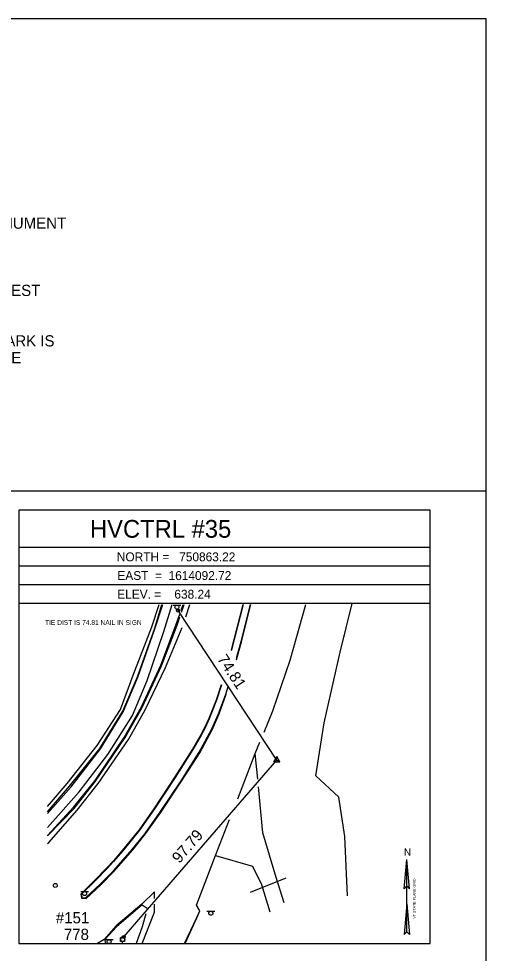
# Model space of a CAD drawing. Extents: x 1612431 to 1613071, y 750572 to 750992.
# Drawn here: x 1612946.1 to 1613071.1, y 750742 to 750992.1 of the extents above; entities that cross this region are included whole.
import ezdxf

# ---------------------------------------------------------------- set-up
doc = ezdxf.new("R2010")
doc.units = 0
for name, color, linetype in [('C_C', 7, 'Continuous'), ('CBP', 7, 'Continuous'), ('CPSM', 7, 'Continuous'), ('DCP', 7, 'Continuous'), ('DD', 7, 'Continuous'), ('Default', 7, 'Continuous'), ('LAWA', 7, 'Continuous'), ('Level 2', 7, 'Continuous'), ('LW', 7, 'Continuous'), ('NBL2', 7, 'Continuous'), ('NNA_P', 7, 'Continuous'), ('PET', 7, 'Continuous'), ('RC', 7, 'Continuous'), ('RDP', 7, 'Continuous'), ('RSW', 7, 'Continuous'), ('SSGN', 7, 'Continuous'), ('U_C', 7, 'Continuous'), ('UP', 7, 'Continuous'), ('USMH', 7, 'Continuous')]:
    doc.layers.add(name, color=color, linetype=linetype)

msp = doc.modelspace()

# ---------------------------------------------------------------- linework, layer by layer
at = {"layer": 'CBP'}
for centre, radius in [((1612988.74, 750833.73), 0.4), ((1612988.74, 750833.73), 0.0533), ((1612974.18, 750746.41), 0.4), ((1612974.18, 750746.41), 0.0533)]:
    msp.add_circle(centre, radius, dxfattribs=at)
at = {"layer": 'CPSM'}
for p, q in [((1613014.31, 750793.31), (1613015.11, 750794.69)), ((1613014.31, 750793.31), (1613015.11, 750793.77)), ((1613014.31, 750793.31), (1613015.91, 750793.31)), ((1613015.91, 750793.31), (1613015.11, 750794.69)), ((1613015.11, 750793.77), (1613015.11, 750794.69)), ((1613015.11, 750793.77), (1613015.11, 750793.77)), ((1613015.11, 750793.77), (1613015.91, 750793.31))]:
    msp.add_line(p, q, dxfattribs=at)
at = {"layer": 'DCP'}
msp.add_lwpolyline([(1613008.11, 750758.43), (1613017.6, 750762.21)], dxfattribs=at)
at = {"layer": 'DD'}
for points in [[(1612989.67, 750833.35), (1612990.37, 750835.4)], [(1612953.85, 750773.49), (1612960.93, 750780.8), (1612966.67, 750788.14), (1612974.54, 750799.79), (1612979.15, 750807.79), (1612984.29, 750818.97), (1612988.48, 750829.89), (1612989.22, 750832.06)]]:
    msp.add_lwpolyline(points, dxfattribs=at)
at = {"layer": 'Default'}
for p, q in [((1613015.11, 750793.77), (1612988.74, 750833.73)), ((1612974.18, 750746.41), (1613015.11, 750793.77))]:
    msp.add_line(p, q, dxfattribs=at)
at = {"layer": 'LAWA'}
for points in [[(1612953.85, 750781.33), (1612959.07, 750787.51), (1612967.13, 750797.64), (1612973.32, 750807.25), (1612976.7, 750816.48), (1612981.68, 750829.38), (1612983.7, 750835.4)], [(1613034.04, 750757.4), (1613033.31, 750773.27), (1613031.74, 750783.85), (1613025.53, 750789.54), (1613027.79, 750803.73), (1613032.1, 750822.61), (1613035.24, 750835.63)]]:
    msp.add_lwpolyline(points, dxfattribs=at)
at = {"layer": 'LW'}
for points in [[(1612953.85, 750779.93), (1612959.69, 750786.76), (1612967.79, 750796.88), (1612973.92, 750806.8), (1612977.86, 750816.05), (1612982.51, 750829.07), (1612984.4, 750835.4)], [(1612989.52, 750833.83), (1612990.08, 750835.4)], [(1612953.85, 750773.61), (1612960.86, 750781.22), (1612966.54, 750788.27), (1612974.34, 750799.76), (1612978.98, 750808), (1612984.15, 750819.13), (1612988.12, 750829.89), (1612989.15, 750832.77)]]:
    msp.add_lwpolyline(points, dxfattribs=at)
at = {"layer": 'NBL2'}
for p, q in [((1612431.13, 750865.8), (1613071.13, 750865.8)), ((1613056.13, 750850.63), (1612946.13, 750850.63)), ((1613056.13, 750845.63), (1612946.13, 750845.63)), ((1613056.13, 750840.63), (1612946.13, 750840.63)), ((1613056.13, 750835.63), (1612946.13, 750835.63))]:
    msp.add_line(p, q, dxfattribs=at)
for points in [[(1612431.13, 750572.13), (1613071.13, 750572.13), (1613071.13, 750992.13), (1612431.13, 750992.13)], [(1612946.13, 750744.63), (1613056.13, 750744.63), (1613056.13, 750860.63), (1612946.13, 750860.63)]]:
    msp.add_lwpolyline(points, close=True, dxfattribs=at)
at = {"layer": 'NNA_P'}
for p, q in [((1613049.19, 750759.34), (1613049.88, 750767.13)), ((1613049.89, 750747.75), (1613049.88, 750767.13)), ((1613050.58, 750759.34), (1613049.88, 750767.13)), ((1613049.19, 750759.34), (1613049.88, 750760.1)), ((1613050.58, 750759.34), (1613049.88, 750760.1)), ((1613049.89, 750755.28), (1613049.17, 750747.12)), ((1613049.88, 750755.28), (1613050.61, 750747.12)), ((1613049.89, 750747.75), (1613049.17, 750747.12)), ((1613049.89, 750747.75), (1613050.61, 750747.12))]:
    msp.add_line(p, q, dxfattribs=at)
at = {"layer": 'PET'}
for points in [[(1612990.77, 750832.08), (1612991.87, 750835.4)], [(1613006.02, 750835.4), (1613002.89, 750823.27), (1613002.89, 750823.27)], [(1613004.35, 750820.6), (1613005.68, 750825.43), (1613008.2, 750835.4)], [(1613011.72, 750801.21), (1613014.06, 750806.93), (1613018.7, 750820.44), (1613022.85, 750835.4)], [(1612953.85, 750771.39), (1612954.14, 750771.67), (1612961.74, 750780.34), (1612967.39, 750787.49), (1612975.48, 750799.24), (1612979.96, 750807.16), (1612985.38, 750818.49), (1612989.83, 750829.25)], [(1613000.23, 750813.89), (1612998.88, 750809.8), (1612996.96, 750804.88), (1612995.8, 750802.39), (1612994.79, 750800.49), (1612992.56, 750796.67), (1612987.87, 750789.24), (1612982.25, 750780.72), (1612978.35, 750775.1), (1612973.74, 750769.59), (1612971.42, 750766.77), (1612969.69, 750764.88), (1612966.47, 750761.64)], [(1612962.75, 750757.91), (1612962.86, 750756.77), (1612964.12, 750756.72), (1612968.07, 750760.39), (1612971.64, 750764.04), (1612976.63, 750769.74), (1612980.05, 750773.99), (1612984.01, 750779.64), (1612989.63, 750788.11), (1612994.54, 750795.73), (1612997.84, 750801.86), (1612999.7, 750806.08), (1613001.62, 750811.36)], [(1613004.67, 750783.42), (1613009.37, 750795.49), (1613010.61, 750798.51)], [(1612990.48, 750744.63), (1612993.77, 750751.6), (1612994.52, 750753.42), (1612993.65, 750754.94), (1612998.74, 750768.23), (1613002.48, 750777.81)], [(1612962.75, 750757.91), (1612966.47, 750761.64)], [(1612982.42, 750756.75), (1612982.43, 750758.53), (1612979.05, 750755.22), (1612972.2, 750749.36), (1612968.94, 750745.77), (1612967.14, 750744.63)], [(1612979.09, 750744.63), (1612982.42, 750753.07), (1612982.42, 750755.19)]]:
    msp.add_lwpolyline(points, dxfattribs=at)
at = {"layer": 'RC'}
for points in [[(1613006.14, 750835.4), (1613003, 750823.24), (1613002.94, 750823)], [(1613004.36, 750821.04), (1613005.57, 750825.45), (1613008.08, 750835.4)], [(1612962.87, 750757.9), (1612963.01, 750756.86), (1612964.01, 750756.9), (1612967.92, 750760.55), (1612971.5, 750764.13), (1612976.47, 750769.83), (1612979.89, 750774.12), (1612983.85, 750779.74), (1612989.53, 750788.23), (1612994.37, 750795.9), (1612997.7, 750801.94), (1612999.54, 750806.12), (1613001.45, 750811.43), (1613002.2, 750813.68)], [(1613000.32, 750813.85), (1612999, 750809.8), (1612997.05, 750804.79), (1612995.94, 750802.34), (1612994.88, 750800.38), (1612992.67, 750796.57), (1612987.95, 750789.11), (1612982.39, 750780.68), (1612978.42, 750775.03), (1612973.94, 750769.44), (1612971.5, 750766.62), (1612969.83, 750764.81), (1612966.65, 750761.53)], [(1612962.87, 750757.9), (1612966.65, 750761.53)], [(1612979.09, 750755.06), (1612972.33, 750749.26)], [(1612979.09, 750755.06), (1612980.49, 750754.1)], [(1612990.61, 750744.63), (1612993.77, 750751.56), (1612994.52, 750753.42)], [(1612980.08, 750752.58), (1612979.14, 750749.09), (1612977.53, 750744.63)], [(1612969.44, 750744.63), (1612969.11, 750745.74), (1612972.33, 750749.26)]]:
    msp.add_lwpolyline(points, dxfattribs=at)
at = {"layer": 'RDP'}
for points in [[(1613010.02, 750788.68), (1613009.37, 750795.49)], [(1613017.09, 750755.57), (1613014.92, 750762.29), (1613011.41, 750774.29), (1613010.22, 750786.63)], [(1612998.74, 750768.23), (1613008.66, 750765.4), (1613011.03, 750760.46), (1613013.29, 750753.11)]]:
    msp.add_lwpolyline(points, dxfattribs=at)
at = {"layer": 'RSW'}
for points in [[(1612953.85, 750775.71), (1612962.29, 750785.29), (1612969.93, 750795.22), (1612976.55, 750805.72), (1612980.48, 750815.03), (1612984.91, 750828.16), (1612987.12, 750835.4)], [(1612953.85, 750779.49), (1612960.13, 750786.56), (1612967.98, 750796.74), (1612974.04, 750806.68), (1612978, 750815.95), (1612982.52, 750828.86), (1612984.64, 750835.4)]]:
    msp.add_lwpolyline(points, dxfattribs=at)
at = {"layer": 'SSGN'}
for p, q in [((1612987.37, 750835.2), (1612989.5, 750835.2)), ((1612988.42, 750834.66), (1612988.42, 750834.66)), ((1612962.68, 750758.56), (1612964.81, 750758.56)), ((1612963.73, 750758.03), (1612963.73, 750758.03)), ((1612996.42, 750753.31), (1612998.56, 750753.31)), ((1612997.48, 750752.77), (1612997.48, 750752.77)), ((1612969.22, 750745.7), (1612971.35, 750745.7)), ((1612970.27, 750745.16), (1612970.27, 750745.16))]:
    msp.add_line(p, q, dxfattribs=at)
for centre in [(1612988.42, 750834.66), (1612963.73, 750758.03), (1612997.48, 750752.77), (1612970.27, 750745.16)]:
    msp.add_circle(centre, 0.533, dxfattribs=at)
at = {"layer": 'UP'}
for p, q in [((1612973.37, 750745.22), (1612973.37, 750746.29)), ((1612973.37, 750746.29), (1612974.44, 750746.29)), ((1612974.44, 750745.22), (1612973.37, 750745.22)), ((1612973.75, 750744.69), (1612973.91, 750745.22)), ((1612974.07, 750746.82), (1612973.91, 750746.29)), ((1612973.91, 750745.76), (1612973.91, 750745.76)), ((1612974.44, 750746.29), (1612974.44, 750745.22))]:
    msp.add_line(p, q, dxfattribs=at)
msp.add_circle((1612973.91, 750745.76), 0.533, dxfattribs=at)
at = {"layer": 'USMH'}
for p, q in [((1612955.89, 750760.2), (1612955.89, 750760.2)), ((1612956.42, 750760.2), (1612956.42, 750760.2))]:
    msp.add_line(p, q, dxfattribs=at)
msp.add_circle((1612955.89, 750760.2), 0.533, dxfattribs=at)

# ---------------------------------------------------------------- texts
at = {"layer": 'C_C'}
msp.add_text('TIE DIST IS 74.81 NAIL IN SIGN', height=1.28, dxfattribs=at).set_placement((1612953.16, 750829.93))
at = {"layer": 'Default'}
for s, rotation, p in [('74.81', 303.4099, (1612999.08, 750820.79)), ('97.79', 49.1657, (1612989.06, 750765.93))]:
    msp.add_text(s, height=3, rotation=rotation, dxfattribs=at).set_placement(p)
at = {"layer": 'Level 2'}
for s, p in [('GENERAL LOCATION, MORRISTOWN, VT. TO REACH FROM THE CIVIL WAR MONUMENT', (1612788.75, 750935.93)), ('TO THE INTERSECTION OF BRIDGE ST CONTINUE STRAIGHT AHEAD AND GO WEST', (1612788.75, 750917.93)), ('TOP OF THE WINGWALL AT THE NORTHEAST CORNER OF THE BRIDGE. THE MARK IS', (1612788.75, 750904.43)), ('5.2 M (17.1 FT) NORTH OF AND ABOUT LEVEL WITH THE CENTERLINE OF BRIDGE', (1612788.75, 750899.93))]:
    msp.add_text(s, height=3, dxfattribs=at).set_placement(p)
at = {"layer": 'NBL2'}
for s, height, p in [('     HVCTRL #35    ', 4.75, (1612956.34, 750853.25)), ('NORTH =   750863.22 ', 2.375, (1612972.35, 750846.94)), ('EAST  =  1614092.72 ', 2.375, (1612972.5, 750841.94)), ('ELEV. =    638.24   ', 2.375, (1612972.46, 750836.94))]:
    msp.add_text(s, height=height, dxfattribs=at).set_placement(p)
at = {"layer": 'NNA_P'}
msp.add_text('N', height=1.97, dxfattribs=at).set_placement((1613049.12, 750768.14))
msp.add_text('VT STATE PLANE GRID', height=0.7, rotation=90.0204, dxfattribs=at).set_placement((1613052.24, 750751.32))
at = {"layer": 'U_C'}
for s, p in [('#151', (1612956.05, 750750.06)), ('778', (1612958.19, 750745.61))]:
    msp.add_text(s, height=3, dxfattribs=at).set_placement(p)

doc.saveas('drawing.dxf')
